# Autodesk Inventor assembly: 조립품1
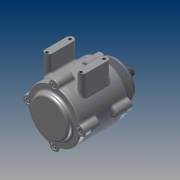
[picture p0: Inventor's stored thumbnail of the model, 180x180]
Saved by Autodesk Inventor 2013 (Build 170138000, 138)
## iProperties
Created: 2015-03
Part Number: 조립품1
Document SubType Name: Assembly
Designer: cad8
Author: cad8
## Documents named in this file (11)
- C:\Documents and Settings\cad8\바탕 화면\450306V1037\조립품1.iam
- C:\Documents and Settings\cad8\바탕 화면\450306V1037\본체1.ipt
- C:\Documents and Settings\cad8\바탕 화면\450306V1037\베어링 6204.ipt
- C:\Documents and Settings\cad8\바탕 화면\450306V1037\오일실.ipt
- C:\Documents and Settings\cad8\바탕 화면\450306V1037\축.ipt
- C:\Documents and Settings\cad8\바탕 화면\450306V1037\커버2.ipt
- C:\Documents and Settings\cad8\바탕 화면\450306V1037\커버.ipt
- C:\Documents and Settings\cad8\바탕 화면\450306V1037\키(4 x 4 x 12).ipt
- C:\Documents and Settings\cad8\바탕 화면\450306V1037\M 4 x 12.ipt
- C:\Documents and Settings\cad8\바탕 화면\450306V1037\V벨트풀리.ipt
- C:\Documents and Settings\cad8\바탕 화면\450306V1037\너트 M12x1.25.ipt
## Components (14 placed, 6 different names)
1. KS B 2023 6204 - 20 x 47 x 14:1
2. KS B 1311 (I) 4 x 4 x 12:1
3. 그루브 풀리1:1
4. KS B 1012 클래스 1 일반 - 미터 M12x1.25:1
5. KS B 2023 6204 - 20 x 47 x 14:2
6. KS B 2804 D D - 20 32 8:2
7. KS B 1003 - 미터 M 4 x 12:2
8. KS B 1003 - 미터 M 4 x 12:3
9. KS B 1003 - 미터 M 4 x 12:4
10. KS B 1003 - 미터 M 4 x 12:5
11. KS B 1003 - 미터 M 4 x 12:6
12. KS B 1003 - 미터 M 4 x 12:7
13. KS B 1003 - 미터 M 4 x 12:8
14. KS B 1003 - 미터 M 4 x 12:9
